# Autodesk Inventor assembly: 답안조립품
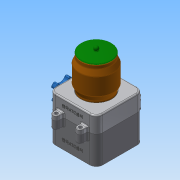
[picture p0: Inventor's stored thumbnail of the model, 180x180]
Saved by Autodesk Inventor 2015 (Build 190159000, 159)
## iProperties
Created: 2018-01
Part Number: 답안조립품
Document SubType Name: Assembly
Designer: user
Author: user
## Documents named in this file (8)
- C:\Users\user\Desktop\480107V1006\답안조립품.iam
- C:\Users\user\Desktop\480107V1006\1.본체.ipt
- C:\Users\user\Desktop\480107V1006\본체커버.ipt
- C:\Users\user\Desktop\480107V1006\핸들축.ipt
- C:\Users\user\Desktop\480107V1006\핸들.ipt
- C:\Users\user\Desktop\480107V1006\볼트 M3x12.ipt
- C:\Users\user\Desktop\480107V1006\용기.ipt
- C:\Users\user\Desktop\480107V1006\용기캡.ipt
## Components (3 placed, 3 different names)
1. 1.본체:1 — 각도:2
2. 핸들축:1 — 각도:1
3. 핸들:1 — 각도:1
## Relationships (2: Angle 2)
- 각도:1 [Angle]: 핸들축:1 ↔ 핸들:1
- 각도:2 [Angle]: 1.본체:1
